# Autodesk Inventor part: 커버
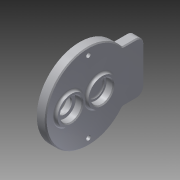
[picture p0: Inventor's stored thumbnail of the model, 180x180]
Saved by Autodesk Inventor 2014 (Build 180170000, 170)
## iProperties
Created: 2016-02
Part Number: 커버
Material: 알루미늄 6061
Document SubType Name: Modeling
Designer: mduedu
Density: 2.71 g/cm^3
Mass: 157.248 g
Surface Area: 178.476 cm^2
Volume: 58.0252 cm^3
Appearance: 알루미늄 - 평지
Author: mduedu
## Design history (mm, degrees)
sketch "스케치1"
  geometry: C1 r 43 at (0, 0); 1 further point
  constraints: 1 centre point, 1 coincident
  dimensions: "d0" = 86 diameter of C1
extrude "돌출1" new body sketch "스케치1" distance "d1" = 9; taper "d2" = 0 deg
sketch "스케치2"
  geometry: C1 r 14 at (0, 11); 1 further point
  constraints: 1 centre point, 1 vertical alignment
  dimensions: "d3" = 28 diameter of C1; "d6" = 11 distance of C1.centre point (0, 0)
extrude "돌출2" join sketch "스케치2" distance "d7" = 3; taper "d8" = 0 deg
sketch "스케치3"
  geometry: C1 r 14 at (0, -20); 1 further point
  constraints: 1 centre point, 1 vertical alignment
  dimensions: "d9" = 28 diameter of C1; "d10" = 20 distance of C1.centre point (0, 0)
extrude "돌출3" join sketch "스케치3" distance "d11" = 3; taper "d12" = 0 deg
hole "구멍1" diameter "d15" = 22; stored, may be unused: countersink angle "d19" = 90 deg, drill point angle "d21" = 0 deg; dims "d13" = 10, "d14" = 10, "d16" = 6, "d17" = 4, "d18" = 2, "d20" = 7
hole "구멍2" diameter "d24" = 18; stored, may be unused: countersink angle "d28" = 90 deg, drill point angle "d30" = 0 deg; dims "d22" = 10, "d23" = 10, "d25" = 6, "d26" = 4, "d27" = 2, "d29" = 1
hole "구멍3" diameter "d33" = 22; stored, may be unused: countersink angle "d37" = 90 deg, drill point angle "d39" = 0 deg; dims "d34" = 6, "d35" = 4, "d36" = 2, "d38" = 7, "d73" = 10, "d74" = 10
sketch "스케치7"
  geometry: L1 (-26, 34.249)-(26, 34.249); L2 (26, 34.249)-(26, 56); L3 (26, 56)-(-26, 56); L4 (-26, 56)-(-26, 34.249); A1 r 43 centre (0, 0) between (-26, 34.249) and (26, 34.249) reference; 1 further point
  constraints: 8 end point, 2 parallel, 2 point on circle, 1 horizontal, 1 perpendicular
  dimensions: "d95" = 52 distance of L2.end L3.end; "d97" = 56 distance from line of L3 point (0, 0)
extrude "돌출5" join sketch "스케치7" stored distance "d98" = 10; taper "d99" = 0 deg
sketch "스케치4"
  geometry: C1 r 14 at (0, -20) reference; C2 r 18 at (0, -20); 1 further point
  constraints: 1 centre point, 1 coincident
  dimensions: "d40" = 36 diameter of C2
extrude "돌출4" join sketch "스케치4" distance "d41" = 4; taper "d42" = 0 deg
hole "구멍4" diameter "d45" = 22; stored, may be unused: countersink angle "d49" = 90 deg, drill point angle "d51" = 0 deg; dims "d43" = 10, "d44" = 10, "d46" = 6, "d47" = 4, "d48" = 2, "d50" = 7
hole "구멍5" diameter "d54" = 15; stored, may be unused: countersink angle "d58" = 90 deg, drill point angle "d60" = 0 deg; dims "d52" = 10, "d53" = 10, "d55" = 6, "d56" = 4, "d57" = 2, "d59" = 7
fillet "모깎기1" dims "d61" = 0.3
fillet "모깎기2" dims "d62" = 2
chamfer "모따기1" distance "d63" = 1; stored, may be unused: second distance "d64" = 2, angle "d65" = 45 deg
fillet "모깎기6" dims "d88" = 2
sketch "스케치5" dims "d67" = 72
  geometry: 4 further points
  constraints: 2 horizontal alignment, 1 coincident, 5 other
  dimensions: "d71" = 360 deg dimension on point (0, 0) point (-36, 0) (derived)
fillet "모깎기4" dims "d75" = 2
sketch "스케치6"
  geometry: 2 further points
hole "구멍6" sketch "스케치6" at (36, 0), (-36, 0) diameter "d76" = 4.5; stored, may be unused: countersink angle "d80" = 90 deg, drill point angle "d82" = 0 deg; dims "d77" = 6, "d78" = 8, "d79" = 4.6, "d81" = 8
fillet "모깎기7" dims "d100" = 8, "d101" = 2
chamfer "모따기2" distance "d90" = 1; stored, may be unused: second distance "d91" = 2, angle "d92" = 45 deg
node "솔리드1"
node "절단 모서리 투영1"
